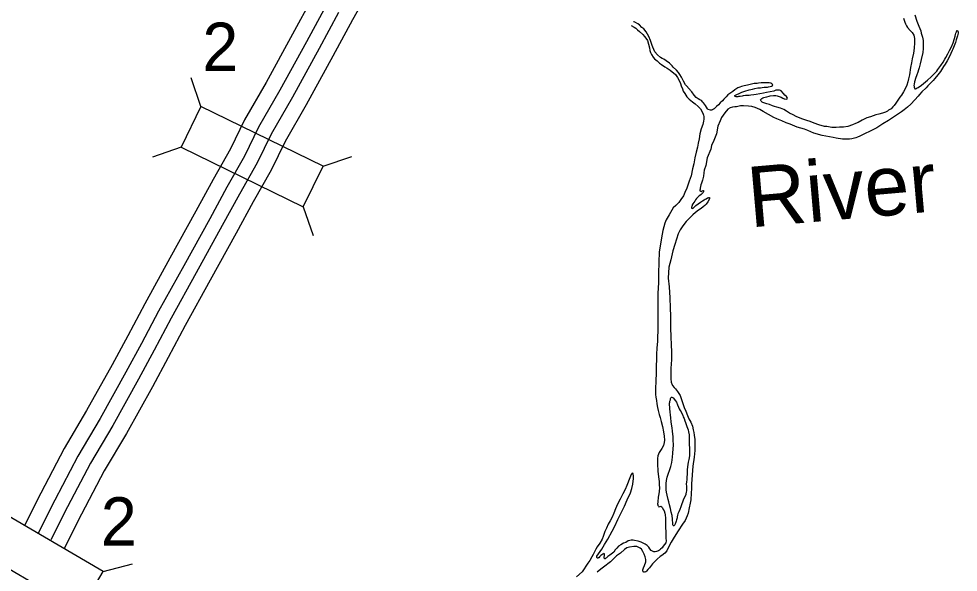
# Model space of a CAD drawing. Extents: x 1373862 to 1377080, y 1164775 to 1170415.
# Drawn here: x 1374478.2 to 1374560.2, y 1170151.1 to 1170199.4 of the extents above; entities that cross this region are included whole.
import ezdxf

# ---------------------------------------------------------------- set-up
doc = ezdxf.new("R2010")
doc.units = 0
doc.layers.add('Default', color=7, linetype='Continuous')

msp = doc.modelspace()

# ---------------------------------------------------------------- linework, layer by layer
at = {"layer": 'Default'}
for p, q in [((1374494.125, 1170191.777), (1374493.267, 1170194.273)), ((1374492.388, 1170188.218), (1374489.892, 1170187.36)), ((1374504.801, 1170186.565), (1374507.298, 1170187.424)), ((1374503.064, 1170183.007), (1374503.923, 1170180.51)), ((1374485.586, 1170151.167), (1374488.14, 1170151.838))]:
    msp.add_line(p, q, dxfattribs=at)
for points in [[(1374509.103, 1170202.483), (1374507.353, 1170199.342), (1374505.645, 1170196.179), (1374503.31, 1170191.919), (1374501.474, 1170188.73), (1374500.25, 1170186.223), (1374498.692, 1170183.466), (1374497.193, 1170180.72), (1374494.928, 1170176.6), (1374492.741, 1170172.639), (1374491.261, 1170169.851), (1374489.885, 1170167.298), (1374487.613, 1170163.218), (1374485.687, 1170159.96), (1374483.711, 1170156.174), (1374482.181, 1170153.16)], [(1374503.846, 1170201.266), (1374502.131, 1170198.091), (1374499.823, 1170193.879), (1374497.939, 1170190.607), (1374496.708, 1170188.086), (1374495.195, 1170185.409), (1374493.685, 1170182.642), (1374491.425, 1170178.53), (1374489.224, 1170174.543), (1374487.734, 1170171.738), (1374486.377, 1170169.22), (1374484.143, 1170165.209), (1374482.189, 1170161.905), (1374480.155, 1170158.005), (1374478.723, 1170155.185)], [(1374505.051, 1170200.605), (1374503.339, 1170197.434), (1374501.022, 1170193.205), (1374499.154, 1170189.962), (1374497.926, 1170187.446), (1374496.397, 1170184.741), (1374494.891, 1170181.981), (1374492.629, 1170177.867), (1374490.433, 1170173.888), (1374488.947, 1170171.089), (1374487.583, 1170168.559), (1374485.336, 1170164.525), (1374483.392, 1170161.236), (1374481.377, 1170157.376), (1374479.898, 1170154.463)], [(1374506.147, 1170200.004), (1374504.437, 1170196.836), (1374502.112, 1170192.593), (1374500.259, 1170189.375), (1374499.032, 1170186.863), (1374497.49, 1170184.134), (1374495.987, 1170181.38), (1374493.724, 1170177.264), (1374491.532, 1170173.293), (1374490.049, 1170170.499), (1374488.679, 1170167.958), (1374486.42, 1170163.903), (1374484.485, 1170160.629), (1374482.489, 1170156.804), (1374481.027, 1170153.925)], [(1374555.474, 1170199.51), (1374555.577, 1170199.16), (1374555.648, 1170198.991), (1374555.72, 1170198.821), (1374555.811, 1170198.671), (1374556.052, 1170198.423), (1374556.224, 1170198.234), (1374556.355, 1170198.005), (1374556.407, 1170197.735), (1374556.421, 1170197.345), (1374556.405, 1170196.874), (1374556.328, 1170196.443), (1374556.222, 1170195.951), (1374556.146, 1170195.59), (1374556.069, 1170195.199), (1374555.974, 1170194.547), (1374555.907, 1170194.196), (1374555.84, 1170193.925), (1374555.742, 1170193.634), (1374555.664, 1170193.453), (1374555.457, 1170193.07), (1374555.28, 1170192.768), (1374555.142, 1170192.587), (1374554.954, 1170192.335), (1374554.797, 1170192.083), (1374554.639, 1170191.872), (1374554.53, 1170191.741), (1374554.371, 1170191.589), (1374554.163, 1170191.457), (1374554.064, 1170191.376), (1374553.885, 1170191.274), (1374553.626, 1170191.212), (1374553.297, 1170191.109), (1374553.038, 1170191.047), (1374552.57, 1170190.893), (1374552.271, 1170190.78), (1374551.854, 1170190.576), (1374551.506, 1170190.393), (1374551.277, 1170190.291), (1374550.998, 1170190.168), (1374550.6, 1170190.044), (1374550.211, 1170189.981), (1374549.872, 1170189.968), (1374549.593, 1170189.946), (1374549.423, 1170189.934), (1374549.203, 1170189.952), (1374548.763, 1170190.029), (1374548.554, 1170190.037), (1374548.063, 1170190.193), (1374547.663, 1170190.33), (1374547.312, 1170190.457), (1374547.012, 1170190.565), (1374546.571, 1170190.711)], [(1374556.441, 1170199.788), (1374556.625, 1170199.229), (1374556.788, 1170198.81), (1374556.961, 1170198.391), (1374557.013, 1170198.201), (1374557.126, 1170197.832), (1374557.178, 1170197.542), (1374557.19, 1170197.251), (1374557.184, 1170196.841), (1374557.136, 1170196.51), (1374556.992, 1170195.878), (1374556.905, 1170195.496), (1374556.828, 1170195.165), (1374556.77, 1170194.974), (1374556.711, 1170194.774), (1374556.633, 1170194.543), (1374556.506, 1170194.231), (1374556.448, 1170194.02), (1374556.419, 1170193.93), (1374556.39, 1170193.739), (1374556.371, 1170193.609), (1374556.382, 1170193.549), (1374556.382, 1170193.509), (1374556.393, 1170193.459), (1374556.423, 1170193.389), (1374556.444, 1170193.339), (1374556.494, 1170193.33), (1374556.553, 1170193.36), (1374556.643, 1170193.401), (1374556.732, 1170193.442), (1374557.04, 1170193.645), (1374557.546, 1170194.09), (1374557.863, 1170194.363), (1374558.061, 1170194.545), (1374558.368, 1170194.878), (1374558.466, 1170195.019), (1374558.723, 1170195.352), (1374558.921, 1170195.644), (1374559.078, 1170195.915), (1374559.157, 1170196.066), (1374559.344, 1170196.388), (1374559.481, 1170196.67), (1374559.658, 1170196.982), (1374559.805, 1170197.344), (1374559.902, 1170197.715), (1374559.96, 1170197.916), (1374559.999, 1170198.066), (1374560.038, 1170198.197), (1374560.077, 1170198.317), (1374560.106, 1170198.388), (1374560.126, 1170198.408), (1374560.176, 1170198.418), (1374560.216, 1170198.369), (1374560.226, 1170198.319), (1374560.237, 1170198.249), (1374560.228, 1170198.189), (1374560.18, 1170197.948), (1374560.073, 1170197.606), (1374559.995, 1170197.365), (1374559.78, 1170196.783), (1374559.711, 1170196.662), (1374559.466, 1170196.139), (1374559.269, 1170195.767), (1374559.092, 1170195.475), (1374558.964, 1170195.264), (1374558.687, 1170194.851), (1374558.45, 1170194.538), (1374558.183, 1170194.215), (1374558.055, 1170194.054), (1374557.857, 1170193.852), (1374557.59, 1170193.579), (1374557.431, 1170193.408), (1374557.075, 1170193.054), (1374556.867, 1170192.832)], [(1374531.699, 1170198.845), (1374531.959, 1170198.718), (1374532.08, 1170198.618), (1374532.251, 1170198.49), (1374532.422, 1170198.321), (1374532.693, 1170198.063), (1374532.845, 1170197.904), (1374532.956, 1170197.745), (1374533.097, 1170197.536), (1374533.282, 1170196.916), (1374533.324, 1170196.686), (1374533.385, 1170196.497), (1374533.456, 1170196.327), (1374533.608, 1170196.098), (1374533.729, 1170195.939)], [(1374540.125, 1170192.809), (1374539.976, 1170192.627), (1374539.768, 1170192.425), (1374539.65, 1170192.264), (1374539.461, 1170192.092), (1374539.313, 1170191.941), (1374539.144, 1170191.789), (1374539.075, 1170191.728), (1374538.936, 1170191.587), (1374538.877, 1170191.536), (1374538.798, 1170191.486), (1374538.708, 1170191.455), (1374538.618, 1170191.464), (1374538.418, 1170191.522), (1374538.357, 1170191.582), (1374538.185, 1170191.871), (1374538.004, 1170192.1), (1374537.943, 1170192.169), (1374537.812, 1170192.298), (1374537.682, 1170192.357), (1374537.522, 1170192.446), (1374537.361, 1170192.555), (1374537.19, 1170192.764), (1374536.968, 1170193.052), (1374536.857, 1170193.181), (1374536.836, 1170193.251), (1374536.443, 1170193.689), (1374536.261, 1170194.008), (1374536.069, 1170194.346), (1374535.927, 1170194.565), (1374535.806, 1170194.755), (1374535.644, 1170194.954), (1374535.353, 1170195.211), (1374535.262, 1170195.331), (1374535.171, 1170195.41), (1374535.03, 1170195.559), (1374534.739, 1170195.767), (1374534.538, 1170195.906), (1374534.378, 1170195.984), (1374534.237, 1170196.073), (1374533.976, 1170196.291), (1374533.754, 1170196.56), (1374533.581, 1170196.959), (1374533.53, 1170197.099), (1374533.387, 1170197.548), (1374533.234, 1170197.887), (1374533.112, 1170198.107), (1374532.981, 1170198.316), (1374532.779, 1170198.554), (1374532.628, 1170198.693), (1374532.427, 1170198.902), (1374532.276, 1170199.011), (1374532.076, 1170199.119), (1374531.936, 1170199.168), (1374531.895, 1170199.182)], [(1374533.729, 1170195.939), (1374533.95, 1170195.77), (1374534.172, 1170195.572), (1374534.342, 1170195.443), (1374534.613, 1170195.245), (1374534.834, 1170195.117), (1374535.085, 1170194.959), (1374535.557, 1170194.572), (1374535.729, 1170194.303), (1374535.871, 1170194.044), (1374535.983, 1170193.805), (1374536.045, 1170193.595), (1374536.157, 1170193.316), (1374536.238, 1170193.116), (1374536.36, 1170192.917), (1374536.552, 1170192.638), (1374536.763, 1170192.41), (1374537.045, 1170192.182), (1374537.276, 1170192.003), (1374537.537, 1170191.785), (1374537.749, 1170191.567), (1374537.951, 1170191.208), (1374538.003, 1170191.028), (1374538.024, 1170190.898), (1374538.035, 1170190.688), (1374537.997, 1170190.497), (1374537.929, 1170190.206), (1374537.783, 1170189.825), (1374537.676, 1170189.403), (1374537.63, 1170188.962), (1374537.544, 1170188.571), (1374537.477, 1170188.22), (1374537.35, 1170187.778), (1374537.235, 1170187.286), (1374537.159, 1170186.785), (1374537.053, 1170186.343), (1374536.918, 1170185.731), (1374536.752, 1170185.259), (1374536.557, 1170184.647), (1374536.381, 1170184.275), (1374536.253, 1170183.983), (1374536.026, 1170183.661), (1374535.839, 1170183.389), (1374535.571, 1170183.146), (1374535.344, 1170182.924), (1374534.999, 1170182.32), (1374534.753, 1170181.867), (1374534.636, 1170181.586), (1374534.441, 1170180.963), (1374534.337, 1170180.321), (1374534.137, 1170179.068), (1374534.104, 1170178.186), (1374534.073, 1170177.195), (1374534.059, 1170176.373), (1374534.017, 1170175.462), (1374534.005, 1170174.51), (1374534.013, 1170173.499), (1374534.021, 1170172.568), (1374533.972, 1170171.245), (1374533.916, 1170170.684), (1374533.891, 1170170.103), (1374533.885, 1170169.592), (1374533.869, 1170169.211), (1374533.862, 1170168.781), (1374533.856, 1170168.3), (1374533.849, 1170167.999), (1374533.842, 1170167.629), (1374533.824, 1170167.288), (1374533.817, 1170167.008), (1374533.819, 1170166.797), (1374533.82, 1170166.617), (1374533.832, 1170166.397), (1374533.884, 1170166.087), (1374533.927, 1170165.797), (1374533.979, 1170165.487), (1374534.031, 1170165.217), (1374534.124, 1170164.877), (1374534.216, 1170164.608), (1374534.319, 1170164.258), (1374534.412, 1170163.828), (1374534.506, 1170163.358), (1374534.569, 1170162.978), (1374534.591, 1170162.638), (1374534.573, 1170162.418), (1374534.495, 1170162.167), (1374534.358, 1170161.905), (1374534.249, 1170161.724), (1374534.141, 1170161.543), (1374534.082, 1170161.422), (1374534.024, 1170161.271), (1374533.986, 1170161.041), (1374533.987, 1170160.81), (1374533.99, 1170160.55), (1374534.015, 1170159.909), (1374534.079, 1170159.429), (1374534.132, 1170159.019), (1374534.144, 1170158.709), (1374534.156, 1170158.488), (1374534.129, 1170158.118), (1374534.072, 1170157.807), (1374534.053, 1170157.646)], [(1374546.571, 1170190.711), (1374546.1, 1170190.897), (1374545.82, 1170191.045), (1374545.509, 1170191.213), (1374545.238, 1170191.361), (1374545.007, 1170191.519), (1374544.727, 1170191.637), (1374544.397, 1170191.714), (1374544.206, 1170191.772), (1374544.036, 1170191.841), (1374543.776, 1170191.959), (1374543.525, 1170192.027), (1374543.355, 1170192.065), (1374543.185, 1170192.144), (1374543.115, 1170192.153), (1374543.024, 1170192.243), (1374542.974, 1170192.353), (1374543.023, 1170192.413), (1374543.102, 1170192.474), (1374543.172, 1170192.525), (1374543.271, 1170192.565), (1374543.391, 1170192.607), (1374543.54, 1170192.628), (1374543.72, 1170192.679), (1374543.829, 1170192.71), (1374544.099, 1170192.733), (1374544.318, 1170192.735), (1374544.418, 1170192.725), (1374544.508, 1170192.686), (1374544.779, 1170192.608), (1374544.939, 1170192.52), (1374545.039, 1170192.45), (1374545.099, 1170192.441), (1374545.269, 1170192.432), (1374545.299, 1170192.443), (1374545.338, 1170192.523), (1374545.258, 1170192.643), (1374545.097, 1170192.781), (1374544.996, 1170192.931), (1374544.784, 1170193.139), (1374544.714, 1170193.169), (1374544.634, 1170193.208), (1374544.564, 1170193.217), (1374544.444, 1170193.216), (1374544.314, 1170193.195), (1374544.145, 1170193.134), (1374543.487, 1170193.008), (1374543.228, 1170192.956), (1374542.919, 1170192.893), (1374542.59, 1170192.84), (1374542.391, 1170192.808), (1374542.122, 1170192.776), (1374541.992, 1170192.755), (1374541.782, 1170192.743), (1374541.663, 1170192.732), (1374541.463, 1170192.71), (1374541.363, 1170192.689), (1374541.194, 1170192.668), (1374541.054, 1170192.647), (1374541.004, 1170192.636), (1374540.855, 1170192.635), (1374540.795, 1170192.644), (1374540.765, 1170192.664), (1374540.744, 1170192.694), (1374540.744, 1170192.744), (1374540.903, 1170192.826), (1374541.102, 1170192.927), (1374541.361, 1170193.04), (1374541.619, 1170193.132), (1374541.978, 1170193.245), (1374542.267, 1170193.288), (1374542.486, 1170193.34), (1374542.755, 1170193.402), (1374542.965, 1170193.414), (1374543.124, 1170193.435), (1374543.284, 1170193.457), (1374543.593, 1170193.479), (1374543.683, 1170193.49), (1374543.833, 1170193.522), (1374543.942, 1170193.553), (1374544.022, 1170193.603), (1374544.041, 1170193.654), (1374544.011, 1170193.693), (1374543.97, 1170193.763), (1374543.87, 1170193.832), (1374543.74, 1170193.851), (1374543.471, 1170193.839), (1374543.021, 1170193.845), (1374542.792, 1170193.813), (1374542.672, 1170193.802), (1374542.423, 1170193.78), (1374542.194, 1170193.738), (1374541.835, 1170193.645), (1374541.556, 1170193.582), (1374541.327, 1170193.52), (1374541.167, 1170193.469), (1374541.008, 1170193.407), (1374540.73, 1170193.225), (1374540.551, 1170193.103), (1374540.313, 1170192.911), (1374540.125, 1170192.809)], [(1374556.867, 1170192.832), (1374556.738, 1170192.691), (1374556.451, 1170192.378), (1374556.115, 1170191.984), (1374555.818, 1170191.722), (1374555.51, 1170191.479), (1374555.282, 1170191.316), (1374555.024, 1170191.144), (1374554.488, 1170190.789), (1374554.16, 1170190.556), (1374553.653, 1170190.261), (1374553.127, 1170189.906), (1374552.431, 1170189.559), (1374552.162, 1170189.447), (1374551.874, 1170189.304), (1374551.645, 1170189.192), (1374551.447, 1170189.1), (1374551.307, 1170189.049), (1374551.178, 1170189.018), (1374550.958, 1170188.966), (1374550.749, 1170188.934), (1374550.5, 1170188.922), (1374550.35, 1170188.921), (1374550.14, 1170188.919), (1374549.57, 1170189.014), (1374549.32, 1170189.072), (1374549, 1170189.119), (1374548.35, 1170189.244), (1374547.64, 1170189.458), (1374547.109, 1170189.674), (1374546.808, 1170189.792), (1374546.178, 1170189.987), (1374545.577, 1170190.232), (1374545.216, 1170190.359), (1374544.826, 1170190.536), (1374544.405, 1170190.702), (1374544.134, 1170190.83), (1374543.202, 1170191.333), (1374542.921, 1170191.521), (1374542.51, 1170191.698), (1374542.21, 1170191.775), (1374541.92, 1170191.823), (1374541.48, 1170191.849), (1374541.221, 1170191.837), (1374540.882, 1170191.764), (1374540.722, 1170191.742), (1374540.523, 1170191.711), (1374540.334, 1170191.659), (1374540.135, 1170191.557), (1374539.858, 1170191.234), (1374539.582, 1170190.831), (1374539.444, 1170190.54), (1374539.258, 1170190.068), (1374539.124, 1170189.385), (1374538.909, 1170188.823), (1374538.713, 1170188.37), (1374538.636, 1170188.059), (1374538.333, 1170187.296), (1374538.208, 1170186.634), (1374538.072, 1170186.222), (1374538.034, 1170185.981), (1374538.006, 1170185.69), (1374537.899, 1170185.349), (1374537.822, 1170185.088), (1374537.773, 1170184.947), (1374537.744, 1170184.807), (1374537.734, 1170184.777), (1374537.725, 1170184.727), (1374537.715, 1170184.667), (1374537.696, 1170184.566), (1374537.677, 1170184.466), (1374537.687, 1170184.416), (1374537.738, 1170184.376), (1374537.798, 1170184.367), (1374537.887, 1170184.408), (1374537.967, 1170184.448), (1374537.987, 1170184.429), (1374538.007, 1170184.409), (1374537.998, 1170184.338), (1374537.968, 1170184.268), (1374537.919, 1170184.208), (1374537.79, 1170184.096), (1374537.691, 1170184.005), (1374537.592, 1170183.934), (1374537.453, 1170183.793), (1374537.384, 1170183.732), (1374537.305, 1170183.632), (1374537.236, 1170183.521), (1374537.147, 1170183.39), (1374537.068, 1170183.269), (1374537.019, 1170183.188), (1374536.999, 1170183.138), (1374536.97, 1170183.048), (1374536.95, 1170182.978), (1374536.951, 1170182.948), (1374536.961, 1170182.908), (1374537.001, 1170182.888), (1374537.051, 1170182.878), (1374537.101, 1170182.899), (1374537.111, 1170182.899), (1374537.17, 1170182.949)], [(1374537.17, 1170182.949), (1374537.339, 1170183.121), (1374537.736, 1170183.425), (1374537.914, 1170183.537), (1374538.063, 1170183.628), (1374538.133, 1170183.689), (1374538.222, 1170183.72), (1374538.361, 1170183.801), (1374538.401, 1170183.811), (1374538.461, 1170183.822), (1374538.501, 1170183.832), (1374538.531, 1170183.832), (1374538.531, 1170183.822), (1374538.532, 1170183.742), (1374538.502, 1170183.662), (1374538.374, 1170183.44), (1374538.226, 1170183.259), (1374538.107, 1170183.138), (1374537.978, 1170183.016), (1374537.81, 1170182.875), (1374537.562, 1170182.712), (1374537.304, 1170182.52), (1374537.076, 1170182.328), (1374536.828, 1170182.095), (1374536.482, 1170181.722), (1374536.195, 1170181.369), (1374535.968, 1170181.006), (1374535.801, 1170180.664), (1374535.636, 1170180.182), (1374535.499, 1170179.74), (1374535.324, 1170179.168), (1374535.141, 1170178.395), (1374534.987, 1170177.733), (1374534.915, 1170176.781), (1374534.991, 1170176.031), (1374535.048, 1170175.08), (1374535.096, 1170174.179), (1374535.112, 1170173.478), (1374535.12, 1170172.397), (1374535.146, 1170171.716), (1374535.173, 1170170.905), (1374535.217, 1170170.405), (1374535.2, 1170170.004), (1374535.193, 1170169.653), (1374535.166, 1170169.293), (1374535.149, 1170168.892), (1374535.142, 1170168.601), (1374535.143, 1170168.431), (1374535.134, 1170168.241), (1374535.146, 1170168.011), (1374535.157, 1170167.911), (1374535.168, 1170167.79), (1374535.179, 1170167.69), (1374535.21, 1170167.601), (1374535.23, 1170167.541), (1374535.281, 1170167.421), (1374535.442, 1170167.242), (1374535.553, 1170167.113), (1374535.735, 1170166.894), (1374535.957, 1170166.535), (1374536.111, 1170166.096), (1374536.315, 1170165.497), (1374536.448, 1170165.178), (1374536.611, 1170164.778), (1374536.723, 1170164.499), (1374536.885, 1170164.19), (1374537.027, 1170163.851), (1374537.1, 1170163.521), (1374537.142, 1170163.291), (1374537.184, 1170163.071), (1374537.247, 1170162.681), (1374537.25, 1170162.34), (1374537.235, 1170161.719), (1374537.179, 1170161.148), (1374537.066, 1170160.346), (1374536.959, 1170158.813), (1374536.952, 1170158.402), (1374536.936, 1170158.001), (1374536.9, 1170157.43), (1374536.843, 1170157.119), (1374536.747, 1170156.708), (1374536.66, 1170156.267), (1374536.582, 1170156.026), (1374536.406, 1170155.604), (1374536.179, 1170155.291), (1374535.785, 1170154.717), (1374535.45, 1170154.163), (1374535.174, 1170153.71), (1374534.928, 1170153.237), (1374534.8, 1170152.976), (1374534.632, 1170152.774), (1374534.365, 1170152.562), (1374534.216, 1170152.46), (1374533.968, 1170152.238), (1374533.829, 1170152.106), (1374533.661, 1170151.955), (1374533.542, 1170151.814), (1374533.374, 1170151.602), (1374533.285, 1170151.471), (1374533.206, 1170151.38), (1374533.137, 1170151.319)], [(1374535.348, 1170162.915), (1374535.304, 1170163.415), (1374535.271, 1170163.715), (1374535.187, 1170164.215), (1374535.144, 1170164.626), (1374535.123, 1170164.826), (1374535.09, 1170165.116), (1374535.058, 1170165.356), (1374535.047, 1170165.476), (1374535.047, 1170165.546), (1374535.036, 1170165.686), (1374535.024, 1170165.856), (1374535.053, 1170165.947), (1374535.063, 1170166.037), (1374535.112, 1170166.148), (1374535.121, 1170166.198), (1374535.131, 1170166.258), (1374535.15, 1170166.318), (1374535.18, 1170166.358), (1374535.22, 1170166.379), (1374535.25, 1170166.379), (1374535.28, 1170166.359), (1374535.33, 1170166.35), (1374535.39, 1170166.29), (1374535.451, 1170166.211), (1374535.552, 1170166.081), (1374535.632, 1170165.962), (1374535.734, 1170165.732), (1374535.816, 1170165.503), (1374535.887, 1170165.373), (1374535.968, 1170165.234), (1374536.049, 1170165.094), (1374536.191, 1170164.785), (1374536.232, 1170164.665), (1374536.303, 1170164.515), (1374536.365, 1170164.326), (1374536.416, 1170164.166), (1374536.487, 1170163.996), (1374536.538, 1170163.836), (1374536.6, 1170163.687), (1374536.651, 1170163.537), (1374536.702, 1170163.347), (1374536.744, 1170163.097), (1374536.756, 1170162.817), (1374536.738, 1170162.566), (1374536.762, 1170162.156), (1374536.773, 1170162.016), (1374536.785, 1170161.786), (1374536.787, 1170161.495), (1374536.769, 1170161.295), (1374536.751, 1170161.094), (1374536.712, 1170160.944), (1374536.654, 1170160.703), (1374536.626, 1170160.512), (1374536.597, 1170160.292), (1374536.569, 1170160.051), (1374536.571, 1170159.831), (1374536.562, 1170159.681), (1374536.545, 1170159.38), (1374536.537, 1170159.18), (1374536.518, 1170158.999), (1374536.5, 1170158.779), (1374536.511, 1170158.599), (1374536.523, 1170158.459), (1374536.514, 1170158.328), (1374536.515, 1170158.198), (1374536.496, 1170158.098), (1374536.467, 1170157.957), (1374536.448, 1170157.867), (1374536.261, 1170157.475), (1374536.027, 1170156.802)], [(1374536.027, 1170156.802), (1374535.939, 1170156.571), (1374535.841, 1170156.38), (1374535.772, 1170156.209), (1374535.743, 1170156.079), (1374535.715, 1170155.928), (1374535.695, 1170155.838), (1374535.647, 1170155.667), (1374535.608, 1170155.557), (1374535.579, 1170155.456), (1374535.559, 1170155.386), (1374535.53, 1170155.336), (1374535.52, 1170155.295), (1374535.491, 1170155.245), (1374535.461, 1170155.195), (1374535.441, 1170155.185), (1374535.412, 1170155.154), (1374535.372, 1170155.144), (1374535.351, 1170155.174), (1374535.331, 1170155.234), (1374535.331, 1170155.294), (1374535.309, 1170155.454), (1374535.308, 1170155.594), (1374535.287, 1170155.724), (1374535.255, 1170156.044), (1374535.182, 1170156.334), (1374535.12, 1170156.674), (1374535.037, 1170156.984), (1374534.975, 1170157.234), (1374534.923, 1170157.453), (1374534.821, 1170157.833), (1374534.779, 1170158.083), (1374534.747, 1170158.303), (1374534.735, 1170158.493), (1374534.752, 1170158.854), (1374534.77, 1170159.115), (1374534.818, 1170159.405), (1374534.935, 1170159.737), (1374535.023, 1170159.978), (1374535.159, 1170160.34), (1374535.226, 1170160.681), (1374535.282, 1170161.152), (1374535.32, 1170161.503), (1374535.357, 1170161.864), (1374535.374, 1170162.184), (1374535.35, 1170162.655), (1374535.348, 1170162.915)], [(1374531.731, 1170158.398), (1374531.827, 1170158.799), (1374531.883, 1170159.27), (1374531.881, 1170159.52), (1374531.87, 1170159.691), (1374531.85, 1170159.71), (1374531.77, 1170159.74), (1374531.671, 1170159.629), (1374531.563, 1170159.347), (1374531.319, 1170158.684), (1374531.153, 1170158.312), (1374530.966, 1170157.94), (1374530.72, 1170157.468), (1374530.504, 1170157.035), (1374530.318, 1170156.643), (1374530.171, 1170156.241), (1374530.014, 1170155.909), (1374529.857, 1170155.597), (1374529.69, 1170155.296), (1374529.523, 1170154.944), (1374529.385, 1170154.662), (1374529.239, 1170154.22), (1374529.141, 1170153.979), (1374528.955, 1170153.627), (1374528.728, 1170153.315), (1374528.6, 1170153.103), (1374528.472, 1170152.872), (1374528.364, 1170152.64), (1374528.265, 1170152.449), (1374528.068, 1170152.117), (1374527.911, 1170151.875), (1374527.418, 1170151.12), (1374526.902, 1170150.695)], [(1374534.053, 1170157.646), (1374534.044, 1170157.516), (1374534.025, 1170157.386), (1374534.017, 1170157.225), (1374534.007, 1170157.155), (1374533.998, 1170157.095), (1374533.998, 1170157.045), (1374534.009, 1170157.005), (1374534.009, 1170156.975), (1374534.019, 1170156.925), (1374534.06, 1170156.855), (1374534.11, 1170156.806), (1374534.21, 1170156.836), (1374534.279, 1170156.857), (1374534.35, 1170156.808), (1374534.39, 1170156.748), (1374534.41, 1170156.708), (1374534.491, 1170156.579), (1374534.552, 1170156.449), (1374534.614, 1170156.259), (1374534.645, 1170156.099), (1374534.677, 1170155.829), (1374534.689, 1170155.569), (1374534.722, 1170154.057), (1374534.733, 1170153.847), (1374534.705, 1170153.676), (1374534.596, 1170153.505), (1374534.488, 1170153.364), (1374534.389, 1170153.223), (1374534.26, 1170153.112), (1374534.161, 1170153.021), (1374534.062, 1170152.97), (1374533.982, 1170152.929), (1374533.893, 1170152.898), (1374533.793, 1170152.877), (1374533.653, 1170152.886), (1374533.443, 1170152.984), (1374533.321, 1170153.144), (1374533.221, 1170153.273), (1374533.07, 1170153.432), (1374532.909, 1170153.551), (1374532.568, 1170153.718), (1374532.458, 1170153.757), (1374532.288, 1170153.816), (1374531.988, 1170153.873), (1374531.848, 1170153.892), (1374531.698, 1170153.891), (1374531.558, 1170153.87), (1374531.429, 1170153.828), (1374531.22, 1170153.706), (1374531.011, 1170153.625), (1374530.773, 1170153.482), (1374530.574, 1170153.36), (1374530.426, 1170153.199), (1374530.287, 1170153.037), (1374530.179, 1170152.856), (1374529.941, 1170152.664), (1374529.822, 1170152.573), (1374529.742, 1170152.522), (1374529.663, 1170152.461), (1374529.604, 1170152.411), (1374529.534, 1170152.35), (1374529.485, 1170152.31), (1374529.425, 1170152.279), (1374529.385, 1170152.269), (1374529.355, 1170152.288), (1374529.335, 1170152.318), (1374529.325, 1170152.348), (1374529.324, 1170152.398), (1374529.334, 1170152.458), (1374529.343, 1170152.519), (1374529.363, 1170152.559), (1374529.372, 1170152.629), (1374529.362, 1170152.669), (1374529.362, 1170152.689), (1374529.301, 1170152.729), (1374529.272, 1170152.708), (1374529.222, 1170152.678), (1374529.192, 1170152.658), (1374529.162, 1170152.637), (1374529.123, 1170152.607), (1374529.043, 1170152.546), (1374528.924, 1170152.445), (1374528.865, 1170152.364), (1374528.815, 1170152.344), (1374528.766, 1170152.313), (1374528.706, 1170152.333), (1374528.675, 1170152.383), (1374528.694, 1170152.493), (1374528.832, 1170152.715), (1374529.119, 1170153.098), (1374529.345, 1170153.51), (1374529.66, 1170153.993), (1374530.034, 1170154.668), (1374530.25, 1170155.11), (1374530.525, 1170155.713), (1374530.8, 1170156.277), (1374531.094, 1170156.88), (1374531.35, 1170157.413), (1374531.624, 1170158.016), (1374531.731, 1170158.398)], [(1374532.859, 1170151.087), (1374532.809, 1170151.096), (1374532.769, 1170151.106), (1374532.749, 1170151.136), (1374532.718, 1170151.196), (1374532.718, 1170151.306), (1374532.776, 1170151.477), (1374532.864, 1170151.688), (1374532.962, 1170151.989), (1374532.97, 1170152.209), (1374532.908, 1170152.439), (1374532.816, 1170152.659), (1374532.714, 1170152.898), (1374532.583, 1170153.107), (1374532.462, 1170153.196), (1374532.252, 1170153.305), (1374532.182, 1170153.354), (1374531.932, 1170153.352), (1374531.553, 1170153.289), (1374531.304, 1170153.216), (1374531.116, 1170153.085), (1374530.749, 1170152.771), (1374530.401, 1170152.528), (1374530.203, 1170152.326), (1374529.886, 1170152.013), (1374529.271, 1170151.547), (1374529.043, 1170151.374), (1374528.726, 1170151.091)], [(1374533.137, 1170151.319), (1374533.028, 1170151.198), (1374532.969, 1170151.138), (1374532.939, 1170151.127), (1374532.889, 1170151.097), (1374532.869, 1170151.087)]]:
    msp.add_lwpolyline(points, dxfattribs=at)
for points in [[(1374504.801, 1170186.565), (1374494.125, 1170191.777), (1374492.388, 1170188.218), (1374503.064, 1170183.007)], [(1374485.586, 1170151.167), (1374475.328, 1170157.16), (1374473.331, 1170153.74), (1374483.589, 1170147.748)]]:
    msp.add_lwpolyline(points, close=True, dxfattribs=at)

# ---------------------------------------------------------------- texts
for p in [(1374494.247, 1170194.884), (1374485.383, 1170153.422)]:
    msp.add_text('2', height=4.224, dxfattribs=at).set_placement(p)
msp.add_text('River', height=5.28, rotation=5, dxfattribs=at).set_placement((1374542.08, 1170181.21))

doc.saveas('drawing.dxf')
